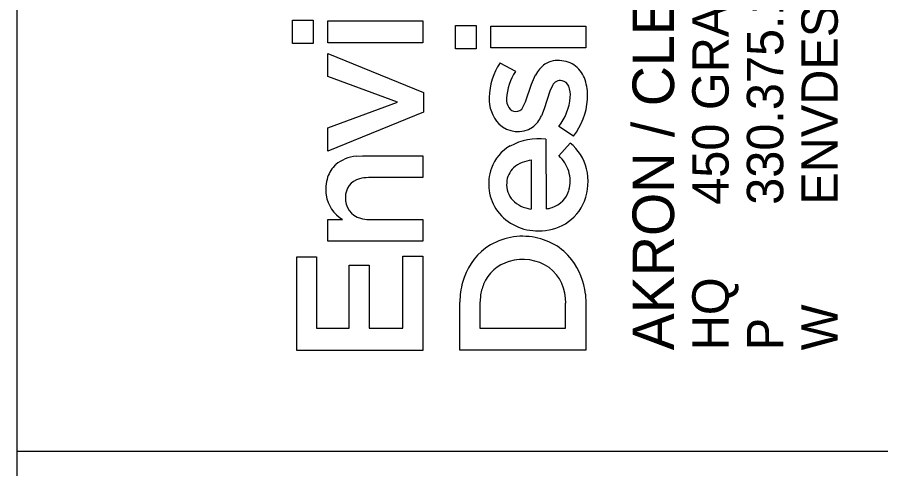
# Model space of a CAD drawing. Extents: x -4.2 to 34, y 0 to 22.
# Drawn here: x 32 to 33.183, y 2.476 to 3.094 of the extents above; entities that cross this region are included whole.
import ezdxf

# ---------------------------------------------------------------- set-up
doc = ezdxf.new("R2010")
doc.units = 0
doc.layers.add('SH_Border', color=7, linetype='Continuous')
doc.layers.add('SH_Data', color=7, linetype='Continuous')

msp = doc.modelspace()

# ---------------------------------------------------------------- linework, layer by layer
at = {"layer": 'SH_Border'}
for p, q in [((32, 0.5), (32, 21.5)), ((32, 2.5), (33.5, 2.5))]:
    msp.add_line(p, q, dxfattribs=at)
at = {"layer": 'SH_Data'}
for p, q in [((32.3771, 3.0582), (32.3771, 3.0903)), ((32.3771, 3.0903), (32.4054, 3.0903)), ((32.4054, 3.0903), (32.4054, 3.0582)), ((32.4254, 3.0594), (32.4254, 3.0893)), ((32.4254, 3.0893), (32.5557, 3.0893)), ((32.5557, 3.0893), (32.5557, 3.0594)), ((32.6005, 3.0511), (32.6005, 3.0832)), ((32.6005, 3.0832), (32.6289, 3.0832)), ((32.6289, 3.0832), (32.6289, 3.0511)), ((32.6489, 3.0523), (32.6489, 3.0822)), ((32.6489, 3.0822), (32.7792, 3.0822)), ((32.7792, 3.0822), (32.7792, 3.0523)), ((32.4054, 3.0582), (32.3771, 3.0582)), ((32.5557, 3.0594), (32.4254, 3.0594)), ((32.4254, 3.0133), (32.4254, 3.0446)), ((32.4254, 3.0446), (32.5567, 2.9913)), ((32.6289, 3.0511), (32.6005, 3.0511)), ((32.7792, 3.0523), (32.6489, 3.0523)), ((32.6615, 3.0321), (32.6827, 3.0203)), ((32.5212, 2.978), (32.4254, 3.0133)), ((32.7048, 3.0026), (32.7104, 3.0153)), ((32.6967, 2.9787), (32.7048, 3.0026)), ((32.7334, 3.001), (32.7298, 2.9933)), ((32.5567, 2.9913), (32.5567, 2.9644)), ((32.7298, 2.9933), (32.7221, 2.9688)), ((32.4254, 2.9429), (32.5212, 2.978)), ((32.693, 2.9712), (32.6967, 2.9787)), ((32.5567, 2.9644), (32.4254, 2.9109)), ((32.7221, 2.9688), (32.7182, 2.9592)), ((32.4254, 2.9109), (32.4254, 2.9429)), ((32.7621, 2.9314), (32.742, 2.9447)), ((32.7245, 2.9275), (32.7246, 2.8319)), ((32.7423, 2.9046), (32.7577, 2.922)), ((32.4644, 2.904), (32.4729, 2.9044)), ((32.4729, 2.9044), (32.5557, 2.9044)), ((32.5557, 2.9044), (32.5557, 2.8746)), ((32.7049, 2.8318), (32.7049, 2.8983)), ((32.5557, 2.8746), (32.4814, 2.8746)), ((32.7036, 2.8317), (32.7049, 2.8318)), ((32.4254, 2.7875), (32.4254, 2.8173)), ((32.4254, 2.8173), (32.4455, 2.8173)), ((32.4822, 2.8173), (32.5557, 2.8173)), ((32.5557, 2.8173), (32.5557, 2.7876)), ((32.5557, 2.7876), (32.4254, 2.7875)), ((32.383, 2.6379), (32.383, 2.766)), ((32.383, 2.766), (32.4101, 2.766)), ((32.4101, 2.766), (32.4101, 2.6683)), ((32.5286, 2.6683), (32.5286, 2.7672)), ((32.5286, 2.7672), (32.5557, 2.7672)), ((32.5557, 2.7672), (32.5557, 2.6379)), ((32.455, 2.6683), (32.455, 2.7549)), ((32.455, 2.7549), (32.4822, 2.7549)), ((32.4822, 2.7549), (32.4822, 2.6683)), ((32.6347, 2.7118), (32.6341, 2.7023)), ((32.7785, 2.715), (32.7792, 2.7021)), ((32.6064, 2.638), (32.6064, 2.704)), ((32.6341, 2.7023), (32.6341, 2.6684)), ((32.7515, 2.6683), (32.7515, 2.7024)), ((32.7792, 2.7021), (32.7792, 2.638)), ((32.4101, 2.6683), (32.455, 2.6683)), ((32.4822, 2.6683), (32.5286, 2.6683)), ((32.6341, 2.6684), (32.7515, 2.6683)), ((32.5557, 2.6379), (32.383, 2.6379)), ((32.7792, 2.638), (32.6064, 2.638))]:
    msp.add_line(p, q, dxfattribs=at)
for points in [[(32.3771, 3.0582), (32.3771, 3.0903), (32.4054, 3.0903), (32.4054, 3.0582)], [(32.4254, 3.0594), (32.4254, 3.0893), (32.5557, 3.0893), (32.5557, 3.0594)], [(32.6005, 3.0511), (32.6005, 3.0832), (32.6289, 3.0832), (32.6289, 3.0511)], [(32.6489, 3.0523), (32.6489, 3.0822), (32.7792, 3.0822), (32.7792, 3.0523)], [(32.4254, 2.9109), (32.4254, 2.9429), (32.5212, 2.978), (32.4254, 3.0133), (32.4254, 3.0446), (32.5567, 2.9913), (32.5567, 2.9644)], [(32.383, 2.6379), (32.383, 2.766), (32.4101, 2.766), (32.4101, 2.6683), (32.455, 2.6683), (32.455, 2.7549), (32.4822, 2.7549), (32.4822, 2.6683), (32.5286, 2.6683), (32.5286, 2.7672), (32.5557, 2.7672), (32.5557, 2.6379)]]:
    msp.add_lwpolyline(points, close=True, dxfattribs=at)
for points in [[(32.6615, 3.0321), (32.6827, 3.0203)], [(32.693, 2.9712), (32.6967, 2.9787), (32.7048, 3.0026), (32.7104, 3.0153)], [(32.7334, 3.001), (32.7298, 2.9933), (32.7221, 2.9688), (32.7182, 2.9592)], [(32.7621, 2.9314), (32.742, 2.9447)], [(32.7245, 2.9275), (32.7246, 2.8319)], [(32.7423, 2.9046), (32.7577, 2.922)], [(32.4644, 2.904), (32.4729, 2.9044), (32.5557, 2.9044), (32.5557, 2.8746), (32.4814, 2.8746)], [(32.7036, 2.8317), (32.7049, 2.8318), (32.7049, 2.8983)], [(32.4254, 2.7875), (32.4254, 2.8173), (32.4455, 2.8173)], [(32.4822, 2.8173), (32.5557, 2.8173), (32.5557, 2.7876), (32.4254, 2.7875)], [(32.7785, 2.715), (32.7792, 2.7021), (32.7792, 2.638), (32.6064, 2.638)], [(32.6347, 2.7118), (32.6341, 2.7023), (32.6341, 2.6684), (32.7515, 2.6683), (32.7515, 2.7024)], [(32.6064, 2.638), (32.6064, 2.704)]]:
    msp.add_lwpolyline(points, dxfattribs=at)
for centre, radius, start, end in [((32.7364, 2.9826), 0.0897, 146.531, 178.7571), ((32.7364, 2.9826), 0.0897, 146.531, 178.7571), ((32.7466, 2.9971), 0.0405, 125.5118, 153.4159), ((32.7466, 2.9971), 0.0405, 125.5118, 153.4159), ((32.7406, 3.0026), 0.0326, 80.1719, 122.5197), ((32.7406, 3.0026), 0.0326, 80.1719, 122.5197), ((32.7428, 2.9982), 0.0367, 47.7934, 84.6892), ((32.7428, 2.9982), 0.0367, 47.7934, 84.6892), ((32.7452, 2.9789), 0.0749, 146.5112, 176.9101), ((32.7452, 2.9789), 0.0749, 146.5112, 176.9101), ((32.7379, 2.9946), 0.0427, 14.9966, 46.2063), ((32.7379, 2.9946), 0.0427, 14.9966, 46.2063), ((32.7438, 2.9963), 0.0114, 76.6609, 155.7053), ((32.7438, 2.9963), 0.0114, 76.6609, 155.7053), ((32.744, 2.9951), 0.0126, 21.5098, 78.5262), ((32.744, 2.9951), 0.0126, 21.5098, 78.5262), ((32.7104, 2.9867), 0.0712, 355.8306, 15.3914), ((32.7104, 2.9867), 0.0712, 355.8306, 15.3914), ((32.7259, 2.9877), 0.0321, 354.5726, 22.068), ((32.7259, 2.9877), 0.0321, 354.5726, 22.068), ((32.6967, 2.9824), 0.0501, 177.5366, 222.7932), ((32.6967, 2.9824), 0.0501, 177.5366, 222.7932), ((32.6931, 2.9823), 0.0228, 178.4747, 211.0868), ((32.6931, 2.9823), 0.0228, 178.4747, 211.0868), ((32.6825, 2.9915), 0.0757, 321.811, 354.7969), ((32.6825, 2.9915), 0.0757, 321.811, 354.7969), ((32.6833, 2.9767), 0.0115, 212.2368, 268.3777), ((32.6833, 2.9767), 0.0115, 212.2368, 268.3777), ((32.6834, 2.9759), 0.0107, 267.716, 333.7337), ((32.6834, 2.9759), 0.0107, 267.716, 333.7337), ((32.6895, 2.9882), 0.0922, 321.9777, 355.8738), ((32.6895, 2.9882), 0.0922, 321.9777, 355.8738), ((32.681, 2.9758), 0.0408, 308.0877, 335.9874), ((32.681, 2.9758), 0.0408, 308.0877, 335.9874), ((32.686, 2.9753), 0.0375, 225.9854, 302.4797), ((32.686, 2.9753), 0.0375, 225.9854, 302.4797), ((32.7152, 2.8441), 0.0838, 83.615, 118.2876), ((32.7152, 2.8441), 0.0838, 83.615, 118.2876), ((32.7024, 2.8691), 0.0558, 118.8308, 160.6244), ((32.7024, 2.8691), 0.0558, 118.8308, 160.6244), ((32.7174, 2.8717), 0.0644, 13.5336, 51.3615), ((32.7174, 2.8717), 0.0644, 13.5336, 51.3615), ((32.4687, 2.8543), 0.0499, 94.9696, 130.2225), ((32.4687, 2.8543), 0.0499, 94.9696, 130.2225), ((32.7038, 2.8656), 0.0549, 19.0357, 45.4406), ((32.7038, 2.8656), 0.0549, 19.0357, 45.4406), ((32.4635, 2.8626), 0.0402, 132.2219, 161.6818), ((32.4635, 2.8626), 0.0402, 132.2219, 161.6818), ((32.7104, 2.8661), 0.0644, 160.5201, 215.7831), ((32.7104, 2.8661), 0.0644, 160.5201, 215.7831), ((32.7005, 2.8663), 0.0298, 132.9851, 177.179), ((32.7005, 2.8663), 0.0298, 132.9851, 177.179), ((32.7079, 2.8561), 0.0424, 94.008, 130.8817), ((32.7079, 2.8561), 0.0424, 94.008, 130.8817), ((32.7107, 2.8697), 0.047, 344.6059, 17.007), ((32.7107, 2.8697), 0.047, 344.6059, 17.007), ((32.7064, 2.8692), 0.0758, 339.3542, 13.3785), ((32.7064, 2.8692), 0.0758, 339.3542, 13.3785), ((32.4787, 2.8582), 0.056, 162.2736, 187.7919), ((32.4787, 2.8582), 0.056, 162.2736, 187.7919), ((32.4748, 2.8487), 0.025, 103.6865, 182.2187), ((32.4748, 2.8487), 0.025, 103.6865, 182.2187), ((32.4811, 2.8286), 0.046, 89.6049, 105.3284), ((32.4811, 2.8286), 0.046, 89.6049, 105.3284), ((32.7017, 2.865), 0.0311, 175.0013, 223.283), ((32.7017, 2.865), 0.0311, 175.0013, 223.283), ((32.7224, 2.8671), 0.035, 288.0077, 343.5508), ((32.7224, 2.8671), 0.035, 288.0077, 343.5508), ((32.4703, 2.858), 0.0476, 188.962, 238.7037), ((32.4703, 2.858), 0.0476, 188.962, 238.7037), ((32.4773, 2.8456), 0.0276, 175.5854, 255.1439), ((32.4773, 2.8456), 0.0276, 175.5854, 255.1439), ((32.7089, 2.8736), 0.0423, 225.0619, 262.7974), ((32.7089, 2.8736), 0.0423, 225.0619, 262.7974), ((32.7189, 2.8652), 0.0626, 300.9427, 338.7323), ((32.7189, 2.8652), 0.0626, 300.9427, 338.7323), ((32.7125, 2.8705), 0.0687, 217.7452, 271.6543), ((32.7125, 2.8705), 0.0687, 217.7452, 271.6543), ((32.7247, 2.8522), 0.0202, 269.7003, 294.8711), ((32.7247, 2.8522), 0.0202, 269.7003, 294.8711), ((32.4818, 2.8595), 0.0422, 254.0916, 270.5284), ((32.4818, 2.8595), 0.0422, 254.0916, 270.5284), ((32.7155, 2.8724), 0.0706, 269.2048, 300.3341), ((32.7155, 2.8724), 0.0706, 269.2048, 300.3341), ((32.6923, 2.7079), 0.0864, 81.194, 125.9984), ((32.6923, 2.7079), 0.0864, 81.194, 125.9984), ((32.6946, 2.7113), 0.0827, 37.8521, 82.402), ((32.6946, 2.7113), 0.0827, 37.8521, 82.402), ((32.6939, 2.7089), 0.0865, 127.2362, 165.148), ((32.6939, 2.7089), 0.0865, 127.2362, 165.148), ((32.6889, 2.7078), 0.054, 106.1881, 157.3861), ((32.6889, 2.7078), 0.054, 106.1881, 157.3861), ((32.6928, 2.6986), 0.0639, 55.6727, 107.2093), ((32.6928, 2.6986), 0.0639, 55.6727, 107.2093), ((32.6859, 2.7057), 0.0931, 5.7333, 37.304), ((32.6859, 2.7057), 0.0931, 5.7333, 37.304), ((32.6929, 2.705), 0.0587, 357.4662, 52.2665), ((32.6929, 2.705), 0.0587, 357.4662, 52.2665), ((32.7143, 2.7028), 0.1078, 164.7861, 179.3704), ((32.7143, 2.7028), 0.1078, 164.7861, 179.3704), ((32.6983, 2.7039), 0.0641, 157.3571, 172.9275), ((32.6983, 2.7039), 0.0641, 157.3571, 172.9275)]:
    msp.add_arc(centre, radius, start, end, dxfattribs=at)

# ---------------------------------------------------------------- texts
for s, height, p in [('450 GRANT ST., AKRON, OH  44311', 0.049846, (32.9749, 2.8374)), ('AKRON / CLEVELAND / COLUMBUS', 0.056969, (32.9001, 2.638)), ('ENVDESIGNGROUP.COM', 0.049846, (33.1244, 2.8374)), ('330.375.1390', 0.049846, (33.0497, 2.8374)), ('HQ ', 0.04985, (32.9749, 2.638)), ('W', 0.0498, (33.1244, 2.638)), ('P', 0.0498, (33.0497, 2.638))]:
    msp.add_text(s, height=height, rotation=90, dxfattribs=at).set_placement(p)

doc.saveas('drawing.dxf')
